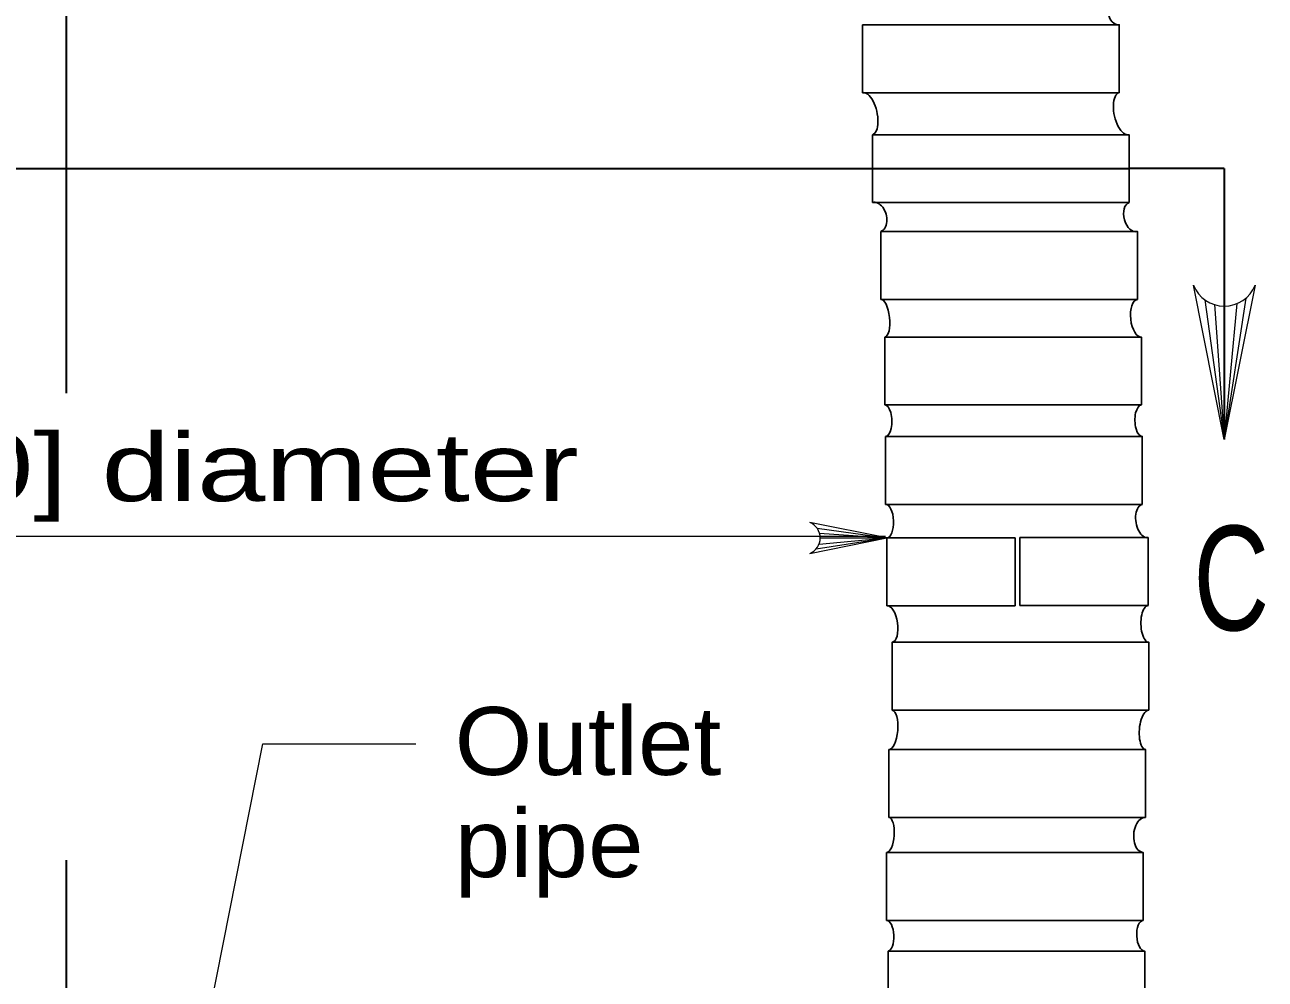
# Model space of a CAD drawing. Extents: x 1083.1 to 1117.1, y 697.4 to 741.4.
# Drawn here: x 1099.373 to 1102.221, y 732.519 to 734.711 of the extents above; entities that cross this region are included whole.
import ezdxf

# ---------------------------------------------------------------- set-up
doc = ezdxf.new("R2010")
doc.units = 0
doc.header["$LTSCALE"] = 0.062
doc.layers.add('1', color=7, linetype='Continuous', lineweight=13)

msp = doc.modelspace()

# ---------------------------------------------------------------- linework, layer by layer
at = {"layer": '1', "lineweight": 35}
for p, q in [((1099.46825, 735.21175), (1099.46825, 733.86533)), ((1097.61867, 734.38058), (1101.90767, 734.38058)), ((1102.127, 734.38058), (1101.90767, 734.38058)), ((1102.127, 734.38058), (1102.127, 733.75883)), ((1099.46825, 732.79267), (1099.46825, 732.65125)), ((1099.46825, 732.65125), (1099.46825, 731.18483))]:
    msp.add_line(p, q, dxfattribs=at)
at = {"layer": '1', "lineweight": 25}
for p, q in [((1101.2965, 734.555), (1101.2965, 734.71092)), ((1101.88575, 734.555), (1101.2965, 734.555)), ((1101.31917, 734.30258), (1101.31917, 734.45858)), ((1101.90842, 734.30258), (1101.31917, 734.30258)), ((1101.33808, 734.08033), (1101.33808, 734.23625)), ((1101.92733, 734.08033), (1101.33808, 734.08033)), ((1101.34758, 733.83792), (1101.34758, 733.99392)), ((1101.93683, 733.83792), (1101.34758, 733.83792)), ((1101.3495, 733.60958), (1101.3495, 733.76558)), ((1101.93867, 733.60958), (1101.3495, 733.60958)), ((1101.64708, 733.5325), (1101.3525, 733.5325)), ((1101.3525, 733.3765), (1101.3525, 733.5325)), ((1101.64708, 733.3765), (1101.64708, 733.5325)), ((1101.952, 733.53317), (1101.65742, 733.53317)), ((1101.65742, 733.37725), (1101.65742, 733.53317)), ((1101.952, 733.37717), (1101.952, 733.53317)), ((1101.64708, 733.3765), (1101.3525, 733.3765)), ((1101.952, 733.37725), (1101.65742, 733.37725)), ((1101.36458, 733.13692), (1101.36458, 733.29292)), ((1101.95383, 733.13692), (1101.36458, 733.13692)), ((1101.357, 732.89058), (1101.357, 733.04658)), ((1101.94625, 732.89058), (1101.357, 732.89058)), ((1101.35133, 732.65425), (1101.35133, 732.81025)), ((1101.94058, 732.65425), (1101.35133, 732.65425)), ((1101.35517, 732.42792), (1101.35517, 732.58392))]:
    msp.add_line(p, q, dxfattribs=at)
at = {"layer": '1'}
for p, q in [((1102.08217, 734.07925), (1102.127, 733.75883)), ((1102.10433, 734.06842), (1102.127, 733.75883)), ((1102.17658, 734.08308), (1102.127, 733.75883)), ((1102.15583, 734.07083), (1102.127, 733.75883)), ((1102.127, 734.06517), (1102.127, 733.75883)), ((1101.19225, 733.55492), (1101.3525, 733.5325)), ((1101.19033, 733.50767), (1101.3525, 733.5325)), ((1101.1965, 733.51808), (1101.3525, 733.5325)), ((1101.19767, 733.54383), (1101.3525, 733.5325)), ((1101.19933, 733.5325), (1101.3525, 733.5325))]:
    msp.add_line(p, q, dxfattribs=at)
at = {"layer": '1', "lineweight": 25}
for points in [[(1101.88575, 734.555), (1101.88575, 734.71092), (1101.2965, 734.71092)], [(1101.90842, 734.30258), (1101.90842, 734.45858), (1101.31917, 734.45858)], [(1101.92733, 734.08033), (1101.92733, 734.23625), (1101.33808, 734.23625)], [(1101.93683, 733.83792), (1101.93683, 733.99392), (1101.34758, 733.99392)], [(1101.93867, 733.60958), (1101.93867, 733.76558), (1101.3495, 733.76558)], [(1101.95383, 733.13692), (1101.95383, 733.29292), (1101.36458, 733.29292)], [(1101.94625, 732.89058), (1101.94625, 733.04658), (1101.357, 733.04658)], [(1101.94058, 732.65425), (1101.94058, 732.81025), (1101.35133, 732.81025)], [(1101.94442, 732.42792), (1101.94442, 732.58392), (1101.35517, 732.58392)]]:
    msp.add_lwpolyline(points, dxfattribs=at)
at = {"layer": '1'}
for points in [[(1102.19783, 734.11283), (1102.127, 733.75883), (1102.05625, 734.11283)], [(1101.1755, 733.49708), (1101.3525, 733.5325), (1101.1755, 733.56783)], [(1097.58842, 733.53633), (1100.79767, 733.53633), (1101.3495, 733.53633)], [(1099.61508, 731.52067), (1099.91942, 733.06), (1100.27075, 733.06)]]:
    msp.add_lwpolyline(points, dxfattribs=at)
for centre, radius, start, end in [((1102.12694, 734.14139), 0.0764, 202.08782, 337.91395), ((1101.16117, 733.53251), 0.0382, 292.08605, 67.91218)]:
    msp.add_arc(centre, radius, start, end, dxfattribs=at)
at = {"layer": '1', "lineweight": 25}
for centre, major_axis, ratio, start_param, end_param in [((1101.88015, 734.74428), (-0.00516, 0.03342), 0.625583, 0.0201562, 3.1617488), ((1101.30784, 734.50678), (0.01104, -0.04828), 0.44347, 0.0147954, 3.1563881), ((1101.89708, 734.50678), (-0.011, 0.04829), 0.462292, 0.0157578, 3.1573505), ((1101.32865, 734.26944), (0.00865, -0.03341), 0.65918, 0.0368482, 3.1784409), ((1101.91789, 734.26944), (-0.00883, 0.03336), 0.611305, 0.0308457, 3.1724383), ((1101.34284, 734.0371), (0.00464, -0.0432), 0.361488, 0.0054302, 3.1470228), ((1101.93208, 734.0371), (-0.00457, 0.04321), 0.463687, 0.0077136, 3.1493062), ((1101.34852, 733.80177), (0.00092, -0.03619), 0.416071, 0.0015877, 3.1431804), ((1101.93775, 733.80176), (-0.00092, 0.03619), 0.442959, 0.0017389, 3.1433316), ((1101.35096, 733.57105), (0.00146, -0.03858), 0.431241, 0.0024799, 3.1440725), ((1101.94535, 733.57139), (-0.00631, 0.03829), 0.551578, 0.016132, 3.1577247), ((1101.35853, 733.33471), (0.0059, -0.04184), 0.435487, 0.0092134, 3.150806), ((1101.95292, 733.33506), (-0.00089, 0.04216), 0.413769, 0.0013076, 3.1429003), ((1101.36081, 733.09174), (0.00372, 0.0452), 0.36206, 3.1374093, 6.2790019), ((1101.95005, 733.09174), (-0.0037, -0.04521), 0.399778, 3.1368155, 6.2784082), ((1101.35419, 732.8504), (0.00278, 0.04019), 0.368842, 3.1379693, 6.2795619), ((1101.94343, 732.8504), (-0.00264, -0.0402), 0.606686, 3.1334441, 6.2750368), ((1101.35325, 732.61907), (0.00184, -0.03519), 0.42781, 0.0033919, 3.1449845), ((1101.94248, 732.61906), (-0.00183, 0.03519), 0.471573, 0.0039281, 3.1455207)]:
    msp.add_ellipse(centre, major_axis=major_axis, ratio=ratio, start_param=start_param, end_param=end_param, dxfattribs=at)

# ---------------------------------------------------------------- texts
at = {"layer": '1'}
for s, height, width, p in [('48" [1200] diameter', 0.156, 1.35, (1098.19675, 733.61708)), ('C', 0.24, 0.75, (1102.05617, 733.32042)), ('Outlet', 0.156, 1.1, (1100.36, 732.98825)), ('pipe', 0.156, 1.1, (1100.36, 732.75358))]:
    msp.add_text(s, height=height, dxfattribs=dict(at, width=width)).set_placement(p)

doc.saveas('drawing.dxf')
